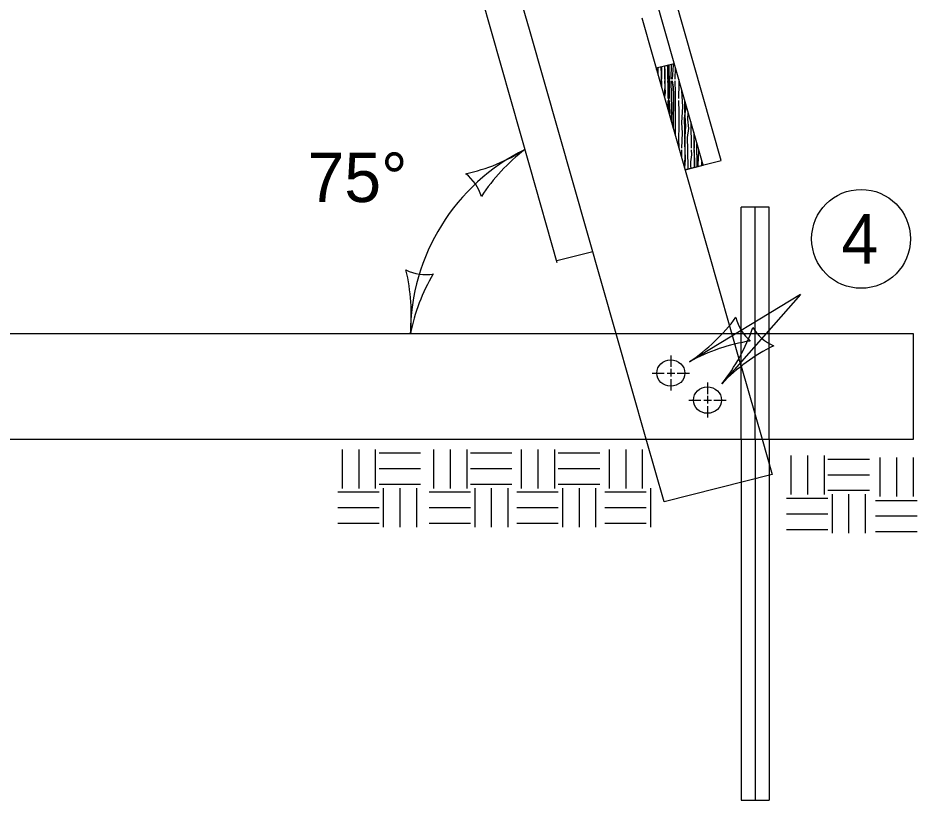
# Model space of a CAD drawing. Extents: x 49991.4 to 50021, y 49987.6 to 50011.4.
# Drawn here: x 50013.065 to 50014.157, y 49992.909 to 49993.859 of the extents above; entities that cross this region are included whole.
import ezdxf

# ---------------------------------------------------------------- set-up
doc = ezdxf.new("R2010")
doc.units = 0
for name, color, linetype in [('Level 1', 7, 'Continuous'), ('Level 2', 7, 'Continuous'), ('Level 3', 7, 'Continuous'), ('Level 4', 7, 'Continuous'), ('Level 5', 7, 'Continuous')]:
    doc.layers.add(name, color=color, linetype=linetype)

msp = doc.modelspace()

# ---------------------------------------------------------------- linework, layer by layer
at = {"layer": 'Level 1'}
for p, q in [((50013.6869, 49993.8419), (50012.9235, 49996.5211)), ((50013.6869, 49993.6773), (50013.4637, 49994.4605)), ((50013.9188, 49993.6855), (50013.8228, 49994.0228)), ((50013.897, 49993.68), (50013.8257, 49993.9301)), ((50013.9433, 49993.4358), (50013.8228, 49993.8584)), ((50013.7914, 49993.4751), (50013.6869, 49993.8419)), ((50013.8399, 49993.7979), (50013.8618, 49993.8034)), ((50013.8399, 49993.7979), (50013.8617, 49993.8034)), ((50013.8751, 49993.6746), (50013.9188, 49993.6855)), ((50013.7199, 49993.5613), (50013.6869, 49993.6773)), ((50013.875, 49993.6744), (50013.8968, 49993.68)), ((50013.9433, 49993.3474), (50013.9433, 49993.6289)), ((50013.9772, 49993.6289), (50013.9433, 49993.6289)), ((50013.9603, 49993.3474), (50013.9603, 49993.6289)), ((50013.9772, 49993.3474), (50013.9772, 49993.6289)), ((50013.7631, 49993.5747), (50013.7193, 49993.5638)), ((50013.6869, 49993.4751), (50010.8912, 49993.4751)), ((50013.7914, 49993.4751), (50013.6869, 49993.4751)), ((50013.8278, 49993.3474), (50013.7914, 49993.4751)), ((50014.1523, 49993.4751), (50013.9321, 49993.4751)), ((50014.1523, 49993.3474), (50014.1523, 49993.4751)), ((50013.9433, 49993.4358), (50013.9685, 49993.3474)), ((50010.8912, 49993.3474), (50013.6869, 49993.3474)), ((50013.6869, 49993.3474), (50013.8278, 49993.3474)), ((50013.9772, 49993.3474), (50014.1523, 49993.3474)), ((50013.4586, 49993.335), (50013.4586, 49993.2877)), ((50013.4788, 49993.335), (50013.4788, 49993.2877)), ((50013.4989, 49993.335), (50013.4989, 49993.2877)), ((50013.5696, 49993.335), (50013.5696, 49993.2877)), ((50013.5898, 49993.335), (50013.5898, 49993.2877)), ((50013.6099, 49993.335), (50013.6099, 49993.2877)), ((50013.6761, 49993.335), (50013.6761, 49993.2877)), ((50013.6963, 49993.335), (50013.6963, 49993.2877)), ((50013.7164, 49993.335), (50013.7164, 49993.2877)), ((50013.7828, 49993.335), (50013.7828, 49993.2877)), ((50013.803, 49993.335), (50013.803, 49993.2877)), ((50013.8231, 49993.335), (50013.8231, 49993.2877)), ((50013.5036, 49993.3306), (50013.5539, 49993.3306)), ((50013.6146, 49993.3306), (50013.6649, 49993.3306)), ((50013.7211, 49993.3306), (50013.7714, 49993.3306)), ((50014.0036, 49993.3276), (50014.0036, 49993.2803)), ((50014.0236, 49993.3276), (50014.0236, 49993.2803)), ((50014.0438, 49993.3276), (50014.0438, 49993.2803)), ((50014.0484, 49993.3232), (50014.0989, 49993.3232)), ((50014.1116, 49993.325), (50014.1116, 49993.2777)), ((50014.1318, 49993.325), (50014.1318, 49993.2777)), ((50014.1519, 49993.325), (50014.1519, 49993.2777)), ((50013.5036, 49993.3117), (50013.5539, 49993.3117)), ((50013.6146, 49993.3117), (50013.6649, 49993.3117)), ((50013.7211, 49993.3117), (50013.7714, 49993.3117)), ((50014.0484, 49993.3042), (50014.0989, 49993.3042)), ((50013.5036, 49993.2928), (50013.5539, 49993.2928)), ((50013.6146, 49993.2928), (50013.6649, 49993.2928)), ((50013.7211, 49993.2928), (50013.7714, 49993.2928)), ((50013.4533, 49993.2833), (50013.5036, 49993.2833)), ((50013.5087, 49993.2881), (50013.5087, 49993.2406)), ((50013.5287, 49993.2881), (50013.5287, 49993.2406)), ((50013.5488, 49993.2881), (50013.5488, 49993.2406)), ((50013.5643, 49993.2833), (50013.6146, 49993.2833)), ((50013.6197, 49993.2881), (50013.6197, 49993.2406)), ((50013.6398, 49993.2881), (50013.6398, 49993.2406)), ((50013.6599, 49993.2881), (50013.6599, 49993.2406)), ((50013.6708, 49993.2833), (50013.7211, 49993.2833)), ((50013.7262, 49993.2881), (50013.7262, 49993.2406)), ((50013.7463, 49993.2881), (50013.7463, 49993.2406)), ((50013.7664, 49993.2881), (50013.7664, 49993.2406)), ((50013.7775, 49993.2833), (50013.8278, 49993.2833)), ((50013.7775, 49993.2833), (50013.8278, 49993.2833)), ((50013.8329, 49993.2881), (50013.8329, 49993.2406)), ((50014.0484, 49993.2853), (50014.0989, 49993.2853)), ((50014.0535, 49993.2805), (50014.0535, 49993.2332)), ((50014.0736, 49993.2805), (50014.0736, 49993.2332)), ((50014.0938, 49993.2805), (50014.0938, 49993.2332)), ((50013.9981, 49993.2759), (50014.0484, 49993.2759)), ((50014.1063, 49993.2731), (50014.1566, 49993.2731)), ((50013.4533, 49993.2643), (50013.5036, 49993.2643)), ((50013.5643, 49993.2643), (50013.6146, 49993.2643)), ((50013.6708, 49993.2643), (50013.7211, 49993.2643)), ((50013.7775, 49993.2643), (50013.8278, 49993.2643)), ((50013.9981, 49993.2569), (50014.0484, 49993.2569)), ((50014.1063, 49993.2543), (50014.1566, 49993.2543)), ((50013.4533, 49993.2453), (50013.5036, 49993.2453)), ((50013.5643, 49993.2453), (50013.6146, 49993.2453)), ((50013.6708, 49993.2453), (50013.7211, 49993.2453)), ((50013.7775, 49993.2453), (50013.8278, 49993.2453)), ((50013.9981, 49993.2379), (50014.0484, 49993.2379)), ((50014.1063, 49993.2353), (50014.1566, 49993.2353))]:
    msp.add_line(p, q, dxfattribs=at)
for points in [[(50013.858, 49993.8025), (50013.8576, 49993.7843)], [(50013.8606, 49993.8031), (50013.8606, 49993.8013), (50013.8595, 49993.7843)], [(50013.8404, 49993.7962), (50013.8404, 49993.7981)], [(50013.8425, 49993.7892), (50013.8424, 49993.7985)], [(50013.8464, 49993.775), (50013.8463, 49993.7906), (50013.8459, 49993.7988), (50013.8459, 49993.7995)], [(50013.8465, 49993.7996), (50013.8463, 49993.7843)], [(50013.8499, 49993.8004), (50013.8502, 49993.7843)], [(50013.8503, 49993.7613), (50013.8507, 49993.7844), (50013.8509, 49993.796), (50013.8502, 49993.8005)], [(50013.8533, 49993.8013), (50013.8535, 49993.7966), (50013.8539, 49993.7808), (50013.8541, 49993.7608)], [(50013.8541, 49993.8015), (50013.854, 49993.7948), (50013.8538, 49993.7843)], [(50013.8554, 49993.8018), (50013.8554, 49993.7966), (50013.8557, 49993.7808), (50013.8559, 49993.7608)], [(50013.863, 49993.7843), (50013.8633, 49993.7982)], [(50013.8633, 49993.7982), (50013.8633, 49993.7982)], [(50013.8463, 49993.7822), (50013.8465, 49993.7745)], [(50013.8502, 49993.7822), (50013.8507, 49993.7679), (50013.8499, 49993.7627)], [(50013.8538, 49993.7822), (50013.8545, 49993.773), (50013.855, 49993.7636), (50013.855, 49993.7453), (50013.855, 49993.7452)], [(50013.8576, 49993.7822), (50013.8584, 49993.748), (50013.8581, 49993.734)], [(50013.8607, 49993.7251), (50013.861, 49993.7648), (50013.8604, 49993.7751), (50013.8595, 49993.7822)], [(50013.8595, 49993.7822), (50013.8604, 49993.7751), (50013.861, 49993.7648), (50013.8607, 49993.7251)], [(50013.8633, 49993.7162), (50013.8633, 49993.7189), (50013.8632, 49993.7349), (50013.8634, 49993.7514), (50013.8633, 49993.7679), (50013.863, 49993.7822)], [(50013.8673, 49993.7838), (50013.8673, 49993.7792), (50013.8671, 49993.7608)], [(50013.8673, 49993.7838), (50013.8673, 49993.7838)], [(50013.8708, 49993.7715), (50013.8708, 49993.7703), (50013.8719, 49993.751), (50013.8708, 49993.7315), (50013.8714, 49993.7193), (50013.8708, 49993.7004)], [(50013.8745, 49993.7588), (50013.8754, 49993.748), (50013.874, 49993.7371), (50013.8742, 49993.7219), (50013.8748, 49993.7004)], [(50013.8519, 49993.7561), (50013.8519, 49993.7561)], [(50013.8541, 49993.7585), (50013.8546, 49993.7459)], [(50013.8559, 49993.7585), (50013.8565, 49993.7442), (50013.8563, 49993.7402)], [(50013.8671, 49993.7585), (50013.8673, 49993.7442), (50013.8676, 49993.7277), (50013.8671, 49993.7114), (50013.8673, 49993.7017)], [(50013.8749, 49993.6769), (50013.8753, 49993.6958), (50013.8749, 49993.7078), (50013.8759, 49993.7273), (50013.8749, 49993.7466), (50013.8749, 49993.7571)], [(50013.855, 49993.7452), (50013.855, 49993.7452)], [(50013.878, 49993.7463), (50013.878, 49993.7465)], [(50013.8786, 49993.6754), (50013.8782, 49993.6984), (50013.878, 49993.7136), (50013.8794, 49993.7244), (50013.8784, 49993.7359), (50013.8788, 49993.7433)], [(50013.882, 49993.7325), (50013.8823, 49993.7004)], [(50013.8857, 49993.7195), (50013.8861, 49993.7004)], [(50013.8863, 49993.6773), (50013.8859, 49993.7132), (50013.886, 49993.7176)], [(50013.8899, 49993.6783), (50013.8894, 49993.7059)], [(50013.8708, 49993.6984), (50013.8708, 49993.6895)], [(50013.8748, 49993.6984), (50013.875, 49993.6867), (50013.8745, 49993.6768)], [(50013.8823, 49993.6984), (50013.8829, 49993.6924), (50013.8818, 49993.6838), (50013.8816, 49993.6787), (50013.8819, 49993.6761)], [(50013.8861, 49993.6984), (50013.8863, 49993.6795), (50013.8862, 49993.6773)], [(50013.8905, 49993.6783), (50013.8909, 49993.6802), (50013.8914, 49993.6885), (50013.8916, 49993.6984)], [(50013.8953, 49993.6796), (50013.8959, 49993.6834)], [(50013.8955, 49993.6843), (50013.8955, 49993.6844)], [(50013.8955, 49993.6798), (50013.8955, 49993.6843)], [(50013.8745, 49993.6768), (50013.8745, 49993.6768)]]:
    msp.add_lwpolyline(points, dxfattribs=at)
for centre in [(50013.8577, 49993.4276), (50013.9022, 49993.3948)]:
    msp.add_ellipse(centre, major_axis=(0.017, 0), ratio=0.940299, dxfattribs=at)
at = {"layer": 'Level 2'}
msp.add_circle((50014.0887, 49993.5905), 0.06, dxfattribs=at)
at = {"layer": 'Level 3'}
for q in [(50013.8805, 49993.4414), (50013.9197, 49993.4147)]:
    msp.add_line((50014.0151, 49993.5231), q, dxfattribs=at)
for centre, radius, start, end in [((50013.7914, 49993.4751), 0.2498, 116.2984, 180), ((50013.5616, 49993.8868), 0.2223, 282.2184, 302.4019), ((50013.8228, 49993.5144), 0.233, 127.5897, 146.8395), ((50013.5754, 49993.626), 0.0548, 16.9012, 52.6235), ((50013.5605, 49993.6019), 0.0548, 243.6603, 279.3827), ((50013.3097, 49993.498), 0.233, 354.3488, 13.5987), ((50013.7599, 49993.4333), 0.2223, 148.9775, 169.161), ((50013.7499, 49993.6344), 0.233, 304.0844, 323.3342), ((50013.9901, 49993.5079), 0.0548, 193.3959, 229.1182), ((50013.7374, 49993.5598), 0.233, 321.4772, 340.727), ((50014.0044, 49993.5109), 0.0548, 210.7887, 246.511), ((50013.9879, 49993.2468), 0.2223, 98.7131, 118.8966), ((50014.0804, 49993.2611), 0.2223, 116.1059, 136.2894)]:
    msp.add_arc(centre, radius, start, end, dxfattribs=at)
at = {"layer": 'Level 4'}
for p, q in [((50013.9321, 49993.4751), (50013.7914, 49993.4751)), ((50013.8495, 49993.2712), (50013.8278, 49993.3474)), ((50013.8278, 49993.3474), (50013.9685, 49993.3474)), ((50013.9433, 49993.3474), (50013.9433, 49992.9094)), ((50013.9603, 49993.3474), (50013.9603, 49992.9094)), ((50013.9685, 49993.3474), (50013.9772, 49993.3474)), ((50013.9685, 49993.3474), (50013.9808, 49993.3043)), ((50013.9772, 49993.3474), (50013.9772, 49992.9094)), ((50013.9808, 49993.3043), (50013.8495, 49993.2712)), ((50013.9433, 49992.9094), (50013.9772, 49992.9094))]:
    msp.add_line(p, q, dxfattribs=at)
at = {"layer": 'Level 5'}
for p, q in [((50013.8576, 49993.4488), (50013.8576, 49993.435)), ((50013.8576, 49993.4327), (50013.8576, 49993.4235)), ((50013.835, 49993.4276), (50013.8497, 49993.4276)), ((50013.8533, 49993.4276), (50013.8627, 49993.4276)), ((50013.8656, 49993.4276), (50013.8803, 49993.4276)), ((50013.8576, 49993.4201), (50013.8576, 49993.4063)), ((50013.9021, 49993.416), (50013.9021, 49993.4022)), ((50013.9021, 49993.3999), (50013.9021, 49993.3907)), ((50013.8795, 49993.3948), (50013.8942, 49993.3948)), ((50013.8978, 49993.3948), (50013.9072, 49993.3948)), ((50013.9101, 49993.3948), (50013.9248, 49993.3948)), ((50013.9021, 49993.3873), (50013.9021, 49993.3735))]:
    msp.add_line(p, q, dxfattribs=at)

# ---------------------------------------------------------------- texts
at = {"layer": 'Level 2'}
for s, p in [('75°', (50013.4167, 49993.6352)), ('4', (50014.0648, 49993.5605))]:
    msp.add_text(s, height=0.06, dxfattribs=at).set_placement(p)

doc.saveas('drawing.dxf')
